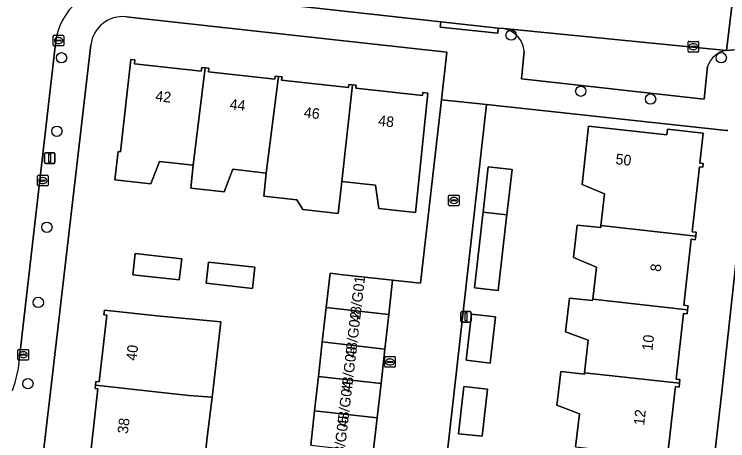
# Model space of a CAD drawing. Extents: x 162396 to 163643, y 386452 to 387406.
# Drawn here: x 162578.5 to 162646, y 386495.4 to 386535.7 of the extents above; entities that cross this region are included whole.
import ezdxf

# ---------------------------------------------------------------- set-up
doc = ezdxf.new("R2010")
doc.units = 0
for name, color, linetype in [('IMGEO_Boom', 7, 'Continuous'), ('IMGEO_Erf', 7, 'Continuous'), ('IMGEO_Kolk', 7, 'Continuous'), ('IMGEO_Lichtmast', 7, 'Continuous'), ('IMGEO_Pand', 7, 'Continuous'), ('IMGEO_Pand_nummerreeks', 7, 'Continuous'), ('IMGEO_Parkeervlak_open', 7, 'Continuous'), ('IMGEO_Rijbaan_lokaal_open', 7, 'Continuous'), ('IMGEO_Voetpad_open', 7, 'Continuous')]:
    doc.layers.add(name, color=color, linetype=linetype)

msp = doc.modelspace()

# ---------------------------------------------------------------- linework, layer by layer
at = {"layer": 'IMGEO_Boom'}
for centre in [(162625.495, 386533.732), (162582.931, 386531.586), (162645.38, 386531.594), (162632.09, 386528.43), (162638.693, 386527.687), (162582.484, 386524.638), (162581.54, 386515.56), (162580.73, 386508.449), (162579.741, 386500.763)]:
    msp.add_circle(centre, 0.489, dxfattribs=at)
at = {"layer": 'IMGEO_Erf'}
for points in [[(162607.615, 386504.705), (162607.979, 386507.957), (162608.344, 386511.21), (162609.301, 386511.103), (162614.269, 386510.545), (162616.92, 386510.257), (162618.897, 386527.607), (162619.412, 386532.131), (162589.057, 386535.472)], [(162585.707, 386532.803), (162581.874, 386500), (162579.329, 386478.218)], [(162646.01, 386524.704), (162645.895, 386524.719), (162623.166, 386527.163), (162620.103, 386500), (162617.525, 386477.133), (162618.44, 386477.031), (162618.731, 386479.362), (162641.052, 386476.87), (162642.754, 386476.691), (162642.817, 386477.198), (162642.901, 386477.877), (162645.441, 386500), (162647.88, 386522.248)], [(162631.598, 386494.787), (162631.951, 386497.917), (162629.827, 386498.725), (162629.97, 386500), (162630.186, 386501.918), (162632.423, 386501.667), (162632.438, 386501.803), (162632.784, 386504.87), (162630.649, 386505.654), (162631.01, 386508.862), (162633.207, 386508.615), (162633.223, 386508.757), (162633.564, 386511.789), (162631.402, 386512.696), (162631.748, 386515.77), (162633.969, 386515.52), (162633.993, 386515.736), (162634.328, 386518.709), (162632.204, 386519.606), (162632.825, 386525.119), (162640.221, 386524.286), (162640.283, 386524.832), (162643.668, 386524.451), (162643.35, 386521.631), (162643.667, 386521.595), (162643.626, 386521.234), (162643.319, 386521.268), (162642.628, 386515.128), (162643.007, 386515.085), (162642.967, 386514.73), (162642.927, 386514.375), (162642.532, 386514.419), (162641.829, 386508.178), (162642.247, 386508.131), (162642.204, 386507.75), (162642.161, 386507.37), (162641.802, 386507.41), (162641.101, 386501.186), (162641.466, 386501.145), (162641.427, 386500.795), (162641.387, 386500.443), (162641.053, 386500.48), (162640.999, 386500), (162640.34, 386494.156)], [(162585.669, 386494.017), (162586.341, 386500), (162586.373, 386500.283), (162586.116, 386500.312), (162586.152, 386500.635), (162586.188, 386500.96), (162586.499, 386500.925), (162587.207, 386507.228), (162586.935, 386507.259), (162586.988, 386507.731), (162591.957, 386507.173), (162597.999, 386506.598), (162597.258, 386500), (162597.201, 386499.488), (162596.724, 386495.666), (162596.369, 386492.508)], [(162606.521, 386494.948), (162606.885, 386498.2), (162607.25, 386501.453), (162607.615, 386504.705)]]:
    msp.add_lwpolyline(points, dxfattribs=at)
for points in [[(162599.131, 386521.041), (162598.336, 386518.915), (162595.163, 386519.267), (162595.402, 386521.423), (162592.203, 386521.778), (162591.392, 386519.667), (162587.985, 386520.044), (162588.281, 386522.714), (162588.514, 386522.688), (162589.484, 386531.439), (162589.862, 386531.397), (162589.82, 386531.013), (162596.161, 386530.311), (162596.201, 386530.672), (162596.538, 386530.634), (162596.875, 386530.597), (162596.837, 386530.248), (162603.11, 386529.553), (162603.145, 386529.862), (162603.472, 386529.826), (162603.802, 386529.789), (162603.766, 386529.464), (162610.08, 386528.764), (162610.113, 386529.068), (162610.468, 386529.029), (162610.821, 386528.99), (162610.79, 386528.705), (162617.09, 386528.007), (162617.123, 386528.305), (162617.591, 386528.253), (162616.432, 386516.942), (162612.957, 386517.327), (162612.636, 386519.548), (162609.458, 386519.9), (162609.121, 386516.853), (162605.775, 386517.223), (162605.212, 386518.16), (162602.072, 386518.508), (162602.313, 386520.689)], [(162625.089, 386516.734), (162625.064, 386516.509), (162624.28, 386509.574), (162622.021, 386509.829), (162622.805, 386516.765), (162622.83, 386516.987), (162623.316, 386521.286), (162625.575, 386521.031)], [(162589.674, 386511.072), (162589.9, 386513.074), (162594.305, 386512.576), (162594.079, 386510.574)], [(162596.608, 386510.264), (162596.834, 386512.266), (162601.239, 386511.768), (162601.013, 386509.766)], [(162623.505, 386502.717), (162621.246, 386502.973), (162621.739, 386507.335), (162623.998, 386507.079)], [(162620.511, 386496.033), (162621.013, 386500.485), (162623.249, 386500.236), (162622.747, 386495.784)]]:
    msp.add_lwpolyline(points, close=True, dxfattribs=at)
msp.add_arc((162588.723, 386532.455), 3.036, 83.67772, 173.4121, dxfattribs=at)
at = {"layer": 'IMGEO_Kolk'}
for p, q in [((162582.147, 386532.796), (162582.147, 386533.648)), ((162582.222, 386533.722), (162583.074, 386533.722)), ((162582.635, 386533.502), (162582.66, 386533.502)), ((162583.148, 386533.648), (162583.148, 386532.796)), ((162583.074, 386532.722), (162582.222, 386532.722)), ((162582.406, 386533.216), (162582.406, 386533.228)), ((162582.844, 386533.179), (162582.446, 386533.179)), ((162582.449, 386533.265), (162582.847, 386533.265)), ((162582.658, 386532.942), (162582.633, 386532.942)), ((162582.89, 386533.228), (162582.89, 386533.216)), ((162642.238, 386532.21), (162642.238, 386533.062)), ((162642.313, 386533.136), (162643.165, 386533.136)), ((162642.497, 386532.63), (162642.497, 386532.642)), ((162642.54, 386532.679), (162642.938, 386532.679)), ((162642.726, 386532.916), (162642.751, 386532.916)), ((162642.981, 386532.642), (162642.981, 386532.63)), ((162643.239, 386533.062), (162643.239, 386532.21)), ((162643.165, 386532.136), (162642.313, 386532.136)), ((162642.935, 386532.593), (162642.537, 386532.593)), ((162642.749, 386532.356), (162642.724, 386532.356)), ((162580.73, 386520.473), (162581.582, 386520.473)), ((162580.655, 386519.547), (162580.655, 386520.399)), ((162580.914, 386519.967), (162580.914, 386519.979)), ((162581.352, 386519.93), (162580.954, 386519.93)), ((162580.957, 386520.016), (162581.355, 386520.016)), ((162581.143, 386520.253), (162581.168, 386520.253)), ((162581.398, 386519.979), (162581.398, 386519.967)), ((162581.656, 386520.399), (162581.656, 386519.547)), ((162581.582, 386519.473), (162580.73, 386519.473)), ((162581.166, 386519.693), (162581.141, 386519.693)), ((162619.567, 386517.668), (162619.567, 386518.52)), ((162619.642, 386518.594), (162620.494, 386518.594)), ((162620.568, 386518.52), (162620.568, 386517.668)), ((162619.826, 386518.088), (162619.826, 386518.1)), ((162620.264, 386518.051), (162619.866, 386518.051)), ((162619.869, 386518.137), (162620.267, 386518.137)), ((162620.078, 386517.814), (162620.053, 386517.814)), ((162620.055, 386518.374), (162620.08, 386518.374)), ((162620.31, 386518.1), (162620.31, 386518.088)), ((162620.494, 386517.594), (162619.642, 386517.594)), ((162578.8, 386503.073), (162578.8, 386503.925)), ((162578.875, 386503.999), (162579.727, 386503.999)), ((162579.288, 386503.779), (162579.313, 386503.779)), ((162579.801, 386503.925), (162579.801, 386503.073)), ((162579.727, 386502.999), (162578.875, 386502.999)), ((162579.059, 386503.493), (162579.059, 386503.505)), ((162579.497, 386503.456), (162579.099, 386503.456)), ((162579.102, 386503.542), (162579.5, 386503.542)), ((162579.311, 386503.219), (162579.286, 386503.219)), ((162579.543, 386503.505), (162579.543, 386503.493)), ((162613.525, 386502.396), (162613.525, 386503.248)), ((162613.6, 386503.322), (162614.452, 386503.322)), ((162614.013, 386503.102), (162614.038, 386503.102)), ((162614.526, 386503.248), (162614.526, 386502.396)), ((162614.452, 386502.322), (162613.6, 386502.322)), ((162613.784, 386502.816), (162613.784, 386502.828)), ((162614.222, 386502.779), (162613.824, 386502.779)), ((162613.827, 386502.865), (162614.225, 386502.865)), ((162614.036, 386502.542), (162614.011, 386502.542)), ((162614.268, 386502.828), (162614.268, 386502.816))]:
    msp.add_line(p, q, dxfattribs=at)
for points in [[(162582.147, 386532.796), (162582.147, 386533.648)], [(162582.222, 386533.722), (162583.074, 386533.722)], [(162583.148, 386533.648), (162583.148, 386532.796)], [(162583.074, 386532.722), (162582.222, 386532.722)], [(162642.238, 386532.21), (162642.238, 386533.062)], [(162642.313, 386533.136), (162643.165, 386533.136)], [(162643.239, 386533.062), (162643.239, 386532.21)], [(162643.165, 386532.136), (162642.313, 386532.136)], [(162580.73, 386520.473), (162581.582, 386520.473)], [(162580.655, 386519.547), (162580.655, 386520.399)], [(162581.656, 386520.399), (162581.656, 386519.547)], [(162581.582, 386519.473), (162580.73, 386519.473)], [(162619.567, 386517.668), (162619.567, 386518.52)], [(162619.642, 386518.594), (162620.494, 386518.594)], [(162620.568, 386518.52), (162620.568, 386517.668)], [(162620.494, 386517.594), (162619.642, 386517.594)], [(162578.8, 386503.073), (162578.8, 386503.925)], [(162578.875, 386503.999), (162579.727, 386503.999)], [(162579.801, 386503.925), (162579.801, 386503.073)], [(162579.727, 386502.999), (162578.875, 386502.999)], [(162613.525, 386502.396), (162613.525, 386503.248)], [(162613.6, 386503.322), (162614.452, 386503.322)], [(162614.526, 386503.248), (162614.526, 386502.396)], [(162614.452, 386502.322), (162613.6, 386502.322)]]:
    msp.add_lwpolyline(points, dxfattribs=at)
for centre, radius, start, end in [((162582.224, 386533.646), 0.0765, 91.55205, 178.44795), ((162582.224, 386533.646), 0.0765, 91.55205, 178.44795), ((162583.072, 386533.646), 0.0765, 1.55205, 88.44795), ((162583.072, 386533.646), 0.0765, 1.55205, 88.44795), ((162582.224, 386532.798), 0.0765, 181.55205, 268.44795), ((162582.224, 386532.798), 0.0765, 181.55205, 268.44795), ((162582.446, 386533.225), 0.0403, 85.87752, 175.75265), ((162582.443, 386533.215), 0.0366, 178.93798, 274.71019), ((162582.847, 386533.222), 0.043, 264.86636, 352.45326), ((162582.851, 386533.227), 0.0386, 1.73085, 96.63898), ((162583.072, 386532.798), 0.0765, 271.55205, 358.44795), ((162583.072, 386532.798), 0.0765, 271.55205, 358.44795), ((162642.315, 386533.06), 0.0765, 91.55205, 178.44795), ((162642.315, 386533.06), 0.0765, 91.55205, 178.44795), ((162642.537, 386532.639), 0.0403, 85.87752, 175.75265), ((162642.534, 386532.629), 0.0366, 178.93798, 274.71019), ((162642.938, 386532.636), 0.043, 264.86636, 352.45326), ((162642.942, 386532.641), 0.0386, 1.73085, 96.63898), ((162643.163, 386533.06), 0.0765, 1.55205, 88.44795), ((162643.163, 386533.06), 0.0765, 1.55205, 88.44795), ((162642.315, 386532.212), 0.0765, 181.55205, 268.44795), ((162642.315, 386532.212), 0.0765, 181.55205, 268.44795), ((162643.163, 386532.212), 0.0765, 271.55205, 358.44795), ((162643.163, 386532.212), 0.0765, 271.55205, 358.44795), ((162580.732, 386520.397), 0.0765, 91.55205, 178.44795), ((162580.732, 386520.397), 0.0765, 91.55205, 178.44795), ((162581.58, 386520.397), 0.0765, 1.55205, 88.44795), ((162581.58, 386520.397), 0.0765, 1.55205, 88.44795), ((162580.954, 386519.976), 0.0403, 85.87752, 175.75265), ((162580.951, 386519.966), 0.0366, 178.93798, 274.71019), ((162581.355, 386519.973), 0.043, 264.86636, 352.45326), ((162581.359, 386519.978), 0.0386, 1.73085, 96.63898), ((162580.732, 386519.549), 0.0765, 181.55205, 268.44795), ((162580.732, 386519.549), 0.0765, 181.55205, 268.44795), ((162581.58, 386519.549), 0.0765, 271.55205, 358.44795), ((162581.58, 386519.549), 0.0765, 271.55205, 358.44795), ((162619.644, 386518.518), 0.0765, 91.55205, 178.44795), ((162619.644, 386518.518), 0.0765, 91.55205, 178.44795), ((162620.492, 386518.518), 0.0765, 1.55205, 88.44795), ((162620.492, 386518.518), 0.0765, 1.55205, 88.44795), ((162619.866, 386518.097), 0.0403, 85.87752, 175.75265), ((162619.863, 386518.087), 0.0366, 178.93798, 274.71019), ((162620.267, 386518.094), 0.043, 264.86636, 352.45326), ((162620.271, 386518.099), 0.0386, 1.73085, 96.63898), ((162619.644, 386517.67), 0.0765, 181.55205, 268.44795), ((162619.644, 386517.67), 0.0765, 181.55205, 268.44795), ((162620.492, 386517.67), 0.0765, 271.55205, 358.44795), ((162620.492, 386517.67), 0.0765, 271.55205, 358.44795), ((162578.877, 386503.923), 0.0765, 91.55205, 178.44795), ((162578.877, 386503.923), 0.0765, 91.55205, 178.44795), ((162579.725, 386503.923), 0.0765, 1.55205, 88.44795), ((162579.725, 386503.923), 0.0765, 1.55205, 88.44795), ((162578.877, 386503.075), 0.0765, 181.55205, 268.44795), ((162578.877, 386503.075), 0.0765, 181.55205, 268.44795), ((162579.099, 386503.502), 0.0403, 85.87752, 175.75265), ((162579.096, 386503.492), 0.0366, 178.93798, 274.71019), ((162579.5, 386503.499), 0.043, 264.86636, 352.45326), ((162579.504, 386503.504), 0.0386, 1.73085, 96.63898), ((162579.725, 386503.075), 0.0765, 271.55205, 358.44795), ((162579.725, 386503.075), 0.0765, 271.55205, 358.44795), ((162613.602, 386503.246), 0.0765, 91.55205, 178.44795), ((162613.602, 386503.246), 0.0765, 91.55205, 178.44795), ((162614.45, 386503.246), 0.0765, 1.55205, 88.44795), ((162614.45, 386503.246), 0.0765, 1.55205, 88.44795), ((162613.602, 386502.398), 0.0765, 181.55205, 268.44795), ((162613.602, 386502.398), 0.0765, 181.55205, 268.44795), ((162613.824, 386502.825), 0.0403, 85.87752, 175.75265), ((162613.821, 386502.815), 0.0366, 178.93798, 274.71019), ((162614.225, 386502.822), 0.043, 264.86636, 352.45326), ((162614.229, 386502.827), 0.0386, 1.73085, 96.63898), ((162614.45, 386502.398), 0.0765, 271.55205, 358.44795), ((162614.45, 386502.398), 0.0765, 271.55205, 358.44795)]:
    msp.add_arc(centre, radius, start, end, dxfattribs=at)
for centre, major_axis, ratio, start_param, end_param in [((162582.634, 386533.222), (-0.387, 0.002), 0.722429, 4.712389, 7.853982), ((162582.659, 386533.222), (-0.39, 0.002), 0.717154, 1.570796, 4.712389), ((162642.725, 386532.636), (-0.387, 0.002), 0.722429, 4.712389, 7.853982), ((162642.75, 386532.636), (-0.39, 0.002), 0.717154, 1.570796, 4.712389), ((162581.142, 386519.973), (-0.387, 0.002), 0.722429, 4.712389, 7.853982), ((162581.167, 386519.973), (-0.39, 0.002), 0.717154, 1.570796, 4.712389), ((162620.054, 386518.094), (-0.387, 0.002), 0.722429, 4.712389, 7.853982), ((162620.079, 386518.094), (-0.39, 0.002), 0.717154, 1.570796, 4.712389), ((162579.287, 386503.499), (-0.387, 0.002), 0.722429, 4.712389, 7.853982), ((162579.312, 386503.499), (-0.39, 0.002), 0.717154, 1.570796, 4.712389), ((162614.012, 386502.822), (-0.387, 0.002), 0.722429, 4.712389, 7.853982), ((162614.037, 386502.822), (-0.39, 0.002), 0.717154, 1.570796, 4.712389)]:
    msp.add_ellipse(centre, major_axis=major_axis, ratio=ratio, start_param=start_param, end_param=end_param, dxfattribs=at)
at = {"layer": 'IMGEO_Lichtmast'}
for p, q in [((162581.318, 386521.702), (162581.318, 386522.502)), ((162581.318, 386522.502), (162581.318, 386521.702)), ((162581.418, 386522.602), (162582.208, 386522.602)), ((162582.208, 386522.602), (162581.418, 386522.602)), ((162582.308, 386522.502), (162582.308, 386521.702)), ((162582.308, 386521.702), (162582.308, 386522.502)), ((162582.208, 386521.602), (162581.418, 386521.602)), ((162581.418, 386521.602), (162582.208, 386521.602)), ((162620.727, 386506.674), (162620.727, 386507.474)), ((162620.727, 386507.474), (162620.727, 386506.674)), ((162620.827, 386507.574), (162621.617, 386507.574)), ((162621.617, 386507.574), (162620.827, 386507.574)), ((162621.717, 386507.474), (162621.717, 386506.674)), ((162621.717, 386506.674), (162621.717, 386507.474)), ((162621.617, 386506.574), (162620.827, 386506.574)), ((162620.827, 386506.574), (162621.617, 386506.574))]:
    msp.add_line(p, q, dxfattribs=at)
for points in [[(162581.738, 386522.477), (162581.888, 386522.477), (162581.888, 386521.727), (162581.738, 386521.727), (162581.738, 386522.477)], [(162621.147, 386507.449), (162621.297, 386507.449), (162621.297, 386506.699), (162621.147, 386506.699), (162621.147, 386507.449)]]:
    msp.add_lwpolyline(points, dxfattribs=at)
for centre, start, end in [((162581.418, 386522.502), 90, 180), ((162581.418, 386522.502), 90, 180), ((162582.208, 386522.502), 0, 90), ((162582.208, 386522.502), 360, 90), ((162581.418, 386521.702), 180, 270), ((162581.418, 386521.702), 180, 270), ((162582.208, 386521.702), 270, 0), ((162582.208, 386521.702), 270, 0), ((162620.827, 386507.474), 90, 180), ((162620.827, 386507.474), 90, 180), ((162621.617, 386507.474), 0, 90), ((162621.617, 386507.474), 360, 90), ((162620.827, 386506.674), 180, 270), ((162620.827, 386506.674), 180, 270), ((162621.617, 386506.674), 270, 0), ((162621.617, 386506.674), 270, 0)]:
    msp.add_arc(centre, 0.1, start, end, dxfattribs=at)
at = {"layer": 'IMGEO_Pand'}
for points in [[(162596.538, 386530.634), (162596.201, 386530.672), (162596.161, 386530.311), (162589.82, 386531.013), (162589.862, 386531.397), (162589.484, 386531.439), (162588.514, 386522.688), (162588.281, 386522.714), (162587.985, 386520.044), (162591.392, 386519.667), (162592.203, 386521.778), (162595.402, 386521.423)], [(162595.402, 386521.423), (162595.163, 386519.267), (162598.336, 386518.915), (162599.131, 386521.041), (162602.313, 386520.689), (162603.472, 386529.826), (162603.145, 386529.862), (162603.11, 386529.553), (162596.837, 386530.248), (162596.875, 386530.597), (162596.538, 386530.634)], [(162602.072, 386518.508), (162605.212, 386518.16), (162605.775, 386517.223), (162609.121, 386516.853), (162609.458, 386519.9), (162610.468, 386529.029), (162610.113, 386529.068), (162610.08, 386528.764), (162603.766, 386529.464), (162603.802, 386529.789), (162603.472, 386529.826), (162602.313, 386520.689)], [(162609.458, 386519.9), (162612.636, 386519.548), (162612.957, 386517.327), (162616.432, 386516.942), (162617.591, 386528.253), (162617.123, 386528.305), (162617.09, 386528.007), (162610.79, 386528.705), (162610.821, 386528.99), (162610.468, 386529.029)], [(162642.967, 386514.73), (162643.007, 386515.085), (162642.628, 386515.128), (162643.319, 386521.268), (162643.626, 386521.234), (162643.667, 386521.595), (162643.35, 386521.631), (162643.668, 386524.451), (162640.283, 386524.832), (162640.221, 386524.286), (162632.825, 386525.119), (162632.204, 386519.606), (162634.328, 386518.709), (162633.993, 386515.736)], [(162625.089, 386516.734), (162625.575, 386521.031), (162623.316, 386521.286), (162622.83, 386516.987)], [(162625.064, 386516.509), (162625.089, 386516.734), (162622.83, 386516.987), (162622.805, 386516.765), (162622.021, 386509.829), (162624.28, 386509.574)], [(162633.993, 386515.736), (162633.969, 386515.52), (162631.748, 386515.77), (162631.402, 386512.696), (162633.564, 386511.789), (162633.223, 386508.757), (162642.204, 386507.75), (162642.247, 386508.131), (162641.829, 386508.178), (162642.532, 386514.419), (162642.927, 386514.375), (162642.967, 386514.73)], [(162594.305, 386512.576), (162589.9, 386513.074), (162589.674, 386511.072), (162594.079, 386510.574)], [(162601.239, 386511.768), (162596.834, 386512.266), (162596.608, 386510.264), (162601.013, 386509.766)], [(162614.269, 386510.545), (162609.301, 386511.103), (162608.344, 386511.21), (162607.979, 386507.957), (162613.904, 386507.293)], [(162641.427, 386500.795), (162641.466, 386501.145), (162641.101, 386501.186), (162641.802, 386507.41), (162642.161, 386507.37), (162642.204, 386507.75), (162633.223, 386508.757), (162633.207, 386508.615), (162631.01, 386508.862), (162630.649, 386505.654), (162632.784, 386504.87), (162632.438, 386501.803)], [(162591.809, 386500), (162594.972, 386499.645), (162597.201, 386499.488), (162597.258, 386500), (162597.999, 386506.598), (162591.957, 386507.173), (162586.988, 386507.731), (162586.935, 386507.259), (162587.207, 386507.228), (162586.499, 386500.925), (162586.188, 386500.96), (162586.152, 386500.635)], [(162613.904, 386507.293), (162607.979, 386507.957), (162607.615, 386504.705), (162613.539, 386504.04)], [(162623.998, 386507.079), (162621.739, 386507.335), (162621.246, 386502.973), (162623.505, 386502.717)], [(162613.174, 386500.788), (162613.539, 386504.04), (162607.615, 386504.705), (162607.25, 386501.453)], [(162632.438, 386501.803), (162632.423, 386501.667), (162630.186, 386501.918), (162629.97, 386500), (162629.827, 386498.725), (162631.951, 386497.917), (162631.598, 386494.787), (162640.683, 386493.768), (162640.722, 386494.113), (162640.34, 386494.156), (162640.999, 386500), (162641.053, 386500.48), (162641.387, 386500.443), (162641.427, 386500.795)], [(162607.25, 386501.453), (162606.885, 386498.2), (162612.81, 386497.536), (162613.174, 386500.788)], [(162597.201, 386499.488), (162594.972, 386499.645), (162591.809, 386500), (162586.152, 386500.635), (162586.116, 386500.312), (162586.373, 386500.283), (162586.341, 386500), (162585.669, 386494.017), (162585.377, 386494.05), (162585.335, 386493.682), (162593.988, 386492.717), (162594.165, 386492.697), (162595.593, 386492.573), (162596.369, 386492.508), (162596.724, 386495.666)], [(162623.249, 386500.236), (162621.013, 386500.485), (162620.511, 386496.033), (162622.747, 386495.784)], [(162612.81, 386497.536), (162606.885, 386498.2), (162606.521, 386494.948), (162612.445, 386494.284)]]:
    msp.add_lwpolyline(points, close=True, dxfattribs=at)
at = {"layer": 'IMGEO_Parkeervlak_open'}
for points in [[(162645.885, 386532.284), (162624.79, 386534.354)], [(162626.737, 386532.221), (162626.483, 386529.596), (162643.752, 386527.675), (162644.081, 386530.77)]]:
    msp.add_lwpolyline(points, dxfattribs=at)
for centre, radius, start, end in [((162624.302, 386531.953), 2.45, 6.27304, 78.50655), ((162646.204, 386530.073), 2.234, 98.19723, 161.81262)]:
    msp.add_arc(centre, radius, start, end, dxfattribs=at)
at = {"layer": 'IMGEO_Rijbaan_lokaal_open'}
for points in [[(162646.614, 386538.331), (162645.885, 386532.284), (162646.587, 386532.351), (162647.481, 386532.53), (162648.432, 386532.856), (162649.066, 386533.064), (162649.424, 386533.182), (162650.383, 386533.596), (162651.301, 386534.093), (162652.171, 386534.67), (162652.314, 386534.776), (162653.783, 386536.092), (162654.327, 386536.802), (162654.805, 386537.557), (162655.214, 386538.352), (162655.55, 386539.18), (162655.811, 386540.036)], [(162589.353, 386538.269), (162618.838, 386534.995), (162624.275, 386534.399), (162624.79, 386534.354), (162645.885, 386532.284), (162646.614, 386538.331)], [(162578.956, 386503.268), (162582.417, 386533.481)]]:
    msp.add_lwpolyline(points, dxfattribs=at)
msp.add_lwpolyline([(162623.166, 386527.163), (162618.897, 386527.607), (162616.92, 386510.257), (162614.269, 386510.545), (162613.904, 386507.293), (162613.539, 386504.04), (162613.174, 386500.788), (162612.81, 386497.536), (162612.445, 386494.284), (162612.08, 386491.031), (162611.715, 386487.779), (162611.351, 386484.527), (162610.986, 386481.275), (162610.613, 386477.95), (162616.049, 386477.317), (162617.393, 386477.15), (162617.525, 386477.133), (162620.103, 386500)], close=True, dxfattribs=at)
for centre, radius, start, end in [((162588.374, 386532.27), 6.079, 80.72897, 168.50655), ((162567.761, 386504.018), 11.22, 339.59389, 356.1671)]:
    msp.add_arc(centre, radius, start, end, dxfattribs=at)
at = {"layer": 'IMGEO_Voetpad_open'}
for points in [[(162624.79, 386534.354), (162624.275, 386534.399), (162624.22, 386533.903), (162618.783, 386534.499), (162618.838, 386534.995), (162589.353, 386538.269)], [(162589.057, 386535.472), (162619.412, 386532.131), (162618.897, 386527.607), (162623.166, 386527.163), (162645.895, 386524.719), (162646.01, 386524.704)], [(162582.417, 386533.481), (162578.956, 386503.268)], [(162578.551, 386471.664), (162579.329, 386478.218), (162581.874, 386500), (162585.707, 386532.803)], [(162644.081, 386530.77), (162643.752, 386527.675), (162626.483, 386529.596), (162626.737, 386532.221)], [(162646.587, 386532.351), (162645.885, 386532.284)]]:
    msp.add_lwpolyline(points, dxfattribs=at)
for points in [[(162618.838, 386534.995), (162618.783, 386534.499), (162624.22, 386533.903), (162624.275, 386534.399)], [(162652.314, 386534.776), (162652.171, 386534.67), (162651.301, 386534.093), (162650.383, 386533.596), (162649.424, 386533.182), (162649.066, 386533.064), (162647.893, 386522.448), (162647.88, 386522.248), (162645.441, 386500), (162642.901, 386477.877), (162642.817, 386477.198), (162645.908, 386476.892), (162646.532, 386481.777), (162648.149, 386496.622), (162648.531, 386500), (162651.092, 386522.672)]]:
    msp.add_lwpolyline(points, close=True, dxfattribs=at)
for centre, radius, start, end in [((162588.374, 386532.27), 6.079, 80.72897, 168.50655), ((162588.723, 386532.455), 3.036, 83.67772, 173.4121), ((162624.302, 386531.953), 2.45, 6.27304, 78.50655), ((162646.204, 386530.073), 2.234, 98.19723, 161.81262), ((162567.761, 386504.018), 11.22, 339.59389, 356.1671)]:
    msp.add_arc(centre, radius, start, end, dxfattribs=at)

# ---------------------------------------------------------------- texts
at = {"layer": 'IMGEO_Pand_nummerreeks'}
for s, rotation, p in [('42', 353.70962, (162591.773, 386527.498)), ('44', 353.70962, (162598.805, 386526.723)), ('46', 353.70962, (162605.835, 386525.948)), ('48', 353.70962, (162612.868, 386525.172)), ('50', 353.57395, (162635.337, 386521.536)), ('8', 83.57317, (162639.646, 386511.31)), ('48/G01', 83.30072, (162611.171, 386506.552)), ('48/G02', 83.30072, (162610.772, 386503.155)), ('10', 83.57394, (162638.866, 386503.853)), ('40', 83.59098, (162590.021, 386502.893)), ('48/G03', 83.30072, (162610.387, 386499.88)), ('48/G04', 83.30072, (162610.002, 386496.599)), ('12', 83.70605, (162638.083, 386496.784)), ('38', 83.39401, (162589.207, 386495.986)), ('48/G05', 83.30072, (162609.617, 386493.317))]:
    msp.add_text(s, height=1, rotation=rotation, dxfattribs=at).set_placement(p)

doc.saveas('drawing.dxf')
